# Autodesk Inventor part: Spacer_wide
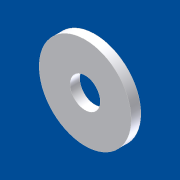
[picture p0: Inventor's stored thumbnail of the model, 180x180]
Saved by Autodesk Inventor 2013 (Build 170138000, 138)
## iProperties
Shininess: 21.0
Length Units: 11269
Angle Units: 11279
Time Units: 11290
Mass Units: 11283
Length Display Precision: 3
Angle Display Precision: 2
Created: 2001-04
Part Number: Spacer_wide
Material: Standard
Document SubType Name: Modellieren
Designer: dl
Density: 1 g/cm^3
Density: 0.0
Volumn: 0.0
Area: 0.0
PropertySet Name: Model Information
Control State: 0
Master: False
Checked Out: False
Author: dl
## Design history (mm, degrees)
body "Solid1"
sketch "Sketch1"
  geometry: C1 r 12.75 at (0, 0); C2 r 4.2 at (0, 0)
  constraints: 2 centre point, 1 concentric
  dimensions: "d0" = 25.5 diameter of C1; "d1" = 8.4 diameter of C2
extrude "Extrusion1" new body sketch "Sketch1" distance "d2" = 2.7; taper "d3" = 0 deg
